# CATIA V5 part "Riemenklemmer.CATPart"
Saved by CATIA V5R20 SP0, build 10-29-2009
Part number: Riemenklemmer
Bounding box of the stored display mesh (mm): x -12 to 12, y -14 to 14, z -8 to 2
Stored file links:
  C:\Users\Andi\Desktop\Offene Projekte\Plasmacutter\Rahmen\Riemenklemmer.CATPart
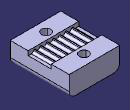
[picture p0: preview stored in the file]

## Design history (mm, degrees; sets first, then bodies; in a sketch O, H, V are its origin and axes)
Body1 (main body)
  Sketch1 on yz-plane, origin (0, 0, 0), H (0, 1, 0), V (0, 0, 1)
    point P1 (-5.5, 0)
    line L1 (-5.5, 0) -> (5.5, 0)
    line L2 (5.5, 0) -> (5.5, 2)
    line L3 (5.5, 2) -> (14, 2)
    line L4 (14, 2) -> (14, -8)
    line L5 (14, -8) -> (-14, -8)
    line L6 (-14, -8) -> (-14, 2)
    point P7 (-14, 2)
    line L7 (-14, 2) -> (-5.5, 2)
    line L8 (-5.5, 2) -> (-5.5, 0)
    distance L5 L3 = 10
    distance L3 L1 = 2
    distance L8 L2 = 11
    distance L6 L4 = 28
    coincidence: P1 H, P7 L3
    horizontal: L1 H, L3 H, L5 H, L7 H
    vertical: L2 V, L4 V, L6 V, L8 V
    symmetry: L6 L4 V, L8 L2 V
  Pad1: profile Sketch1, direction (1, 0, 0), length 12, mirrored extent
  Sketch2 on zx-plane, origin (0, 0, 0), H (-1, 0, 0), V (0, 0, 1)
    arc A1 centre (-1.5, 1.13) radius 1.13 from (-1.5, 0) to (-0.3951, 0.8929) ccw
    point P1 (-1.5, 1.13)
    line L1 (-0.1018, 1.13) -> (0.1018, 1.13)
    line L2 (1.5, 0) -> (-1.5, 0)
    arc A2 centre (-0.1018, 0.83) radius 0.3 from (-0.3951, 0.8929) to (-0.1018, 1.13) cw
    arc A3 centre (1.5, 1.13) radius 1.13 from (0.3951, 0.8929) to (1.5, 0) ccw
    arc A4 centre (0.1018, 0.83) radius 0.3 from (0.3951, 0.8929) to (0.1018, 1.13) ccw
    distance P1 V = 1.5
    distance L1 H = 1.13
    radius A2 = 0.3
    tangency: A1 H, L2 A1, A2 L1, A2 A1, A4 A3, A4 L1
    horizontal: L1 H
    coincidence: P1 L1, O L2
    symmetry: A4 A2 V, A3 A1 V
  Pad2: profile Sketch2, direction (0, 1, 0), up to the existing solid (limit type 2), opposite side up to the existing solid (limit type 2)
  RectPattern1: of Pad2, direction 1 instances 1, spacing 20, along zx-plane, direction 2 instances 7, spacing 3, along zx-plane, Nv 4
  Sketch3 on face of Pad1 from Sketch1.L5, origin (0.3261, 11.1206, -8), H (1, 0, 0), V (0, -1, 0)
    point P1 (-0.3261, 2.1206)
    reference intersected line E1 through (0, 11.1206) direction (1, 0) from zx-plane
    reference intersected line E2 through (-0.3261, 0) direction (0, 1) from yz-plane
    distance P1 E1 = 9
    coincidence: P1 E2
  Hole1: placed by Sketch3, at (0, 9, -8) direction (0, 0, 1), diameter 4.3, through (limit type 6), counterbore diameter 8, counterbore depth 4.5
  Mirror1: of Hole1, about zx-plane
  Fillet1: radius 3, on edge [start face of Pad1 | face of Pad1 from Sketch1.L5]; edge [face of Pad1 from Sketch1.L5 | end face of Pad1]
